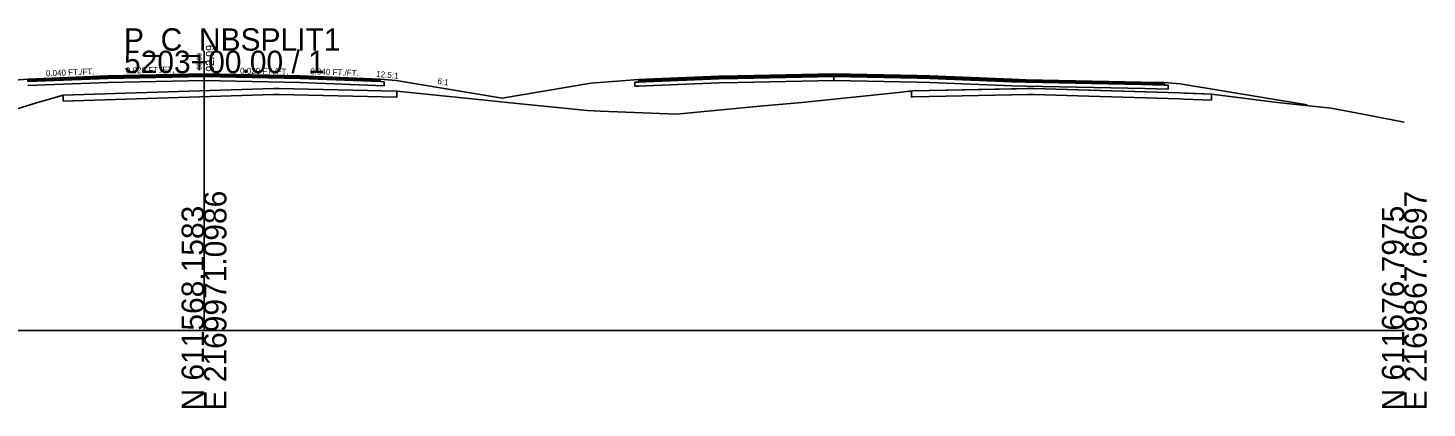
# Model space of a CAD drawing. Extents: x -26 to 1303, y -3010 to 12038.
# Drawn here: x 1128 to 1302.8, y 2490.3 to 2537.8 of the extents above; entities that cross this region are included whole.
import ezdxf

# ---------------------------------------------------------------- set-up
doc = ezdxf.new("R2010")
doc.units = 0
for name, color, linetype in [('RD_GPK_XS_Cell', 7, 'Continuous'), ('RD_XS_Base', 7, 'Continuous'), ('RD_XS_ExGround', 7, 'Continuous'), ('RD_XS_ExPaveRet', 7, 'Continuous'), ('RD_XS_Greenside', 7, 'Continuous'), ('RD_XS_Pave', 7, 'Continuous'), ('RD_XS_PaveOvlay_CP', 7, 'Continuous'), ('RD_XS_TieSlope', 7, 'Continuous'), ('RD_XS_TX_Elev_EX', 7, 'Continuous'), ('RD_XS_TX_Elev_PR', 7, 'Continuous'), ('RD_XS_TX_ShdSlope', 7, 'Continuous'), ('RD_XS_TX_Slope', 7, 'Continuous')]:
    doc.layers.add(name, color=color, linetype=linetype)

msp = doc.modelspace()

# ---------------------------------------------------------------- linework, layer by layer
at = {"layer": 'RD_GPK_XS_Cell'}
for p, q in [((1150, 2500), (1150, 2535)), ((1000, 2500), (1150, 2500)), ((1150, 2500), (1300, 2500))]:
    msp.add_line(p, q, dxfattribs=at)
at = {"layer": 'RD_XS_Base'}
for p, q in [((1150, 2531.77), (1138, 2531.53)), ((1150, 2531.77), (1150, 2531.93)), ((1150, 2531.93), (1150, 2531.93)), ((1150, 2531.93), (1150, 2531.93)), ((1150, 2531.93), (1150, 2531.27)), ((1150, 2531.27), (1150, 2531.77)), ((1150, 2531.77), (1150, 2531.77)), ((1150, 2531.77), (1150, 2531.77)), ((1150, 2531.77), (1150, 2531.77)), ((1162, 2531.53), (1150, 2531.77)), ((1228.71, 2531.77), (1216.71, 2531.53)), ((1228.71, 2531.79), (1228.71, 2531.93)), ((1228.71, 2531.93), (1228.71, 2531.35)), ((1228.71, 2531.77), (1228.71, 2531.79)), ((1228.71, 2531.77), (1228.71, 2531.77)), ((1239.11, 2531.56), (1228.71, 2531.77)), ((1228.71, 2531.77), (1228.71, 2531.77)), ((1228.71, 2531.33), (1228.71, 2531.77)), ((1138, 2531.53), (1128, 2531.13)), ((1128, 2531.13), (1128, 2531.13)), ((1128, 2530.63), (1138, 2531.03)), ((1128, 2530.63), (1128, 2530.63)), ((1138, 2531.53), (1138, 2531.53)), ((1138, 2531.03), (1150, 2531.27)), ((1138, 2531.03), (1138, 2531.03)), ((1150, 2531.27), (1150, 2531.27)), ((1150, 2531.27), (1150, 2531.27)), ((1150, 2531.27), (1162, 2531.03)), ((1172, 2531.13), (1162, 2531.53)), ((1162, 2531.03), (1172.5, 2530.61)), ((1164, 2531.45), (1164, 2531.45)), ((1164, 2530.95), (1164, 2530.95)), ((1172.5, 2531.11), (1172, 2531.13)), ((1172, 2531.13), (1172, 2531.13)), ((1172.5, 2530.61), (1172.5, 2531.11)), ((1172.5, 2531.11), (1172.5, 2531.11)), ((1203.89, 2531.06), (1203.85, 2531.06)), ((1203.85, 2531.06), (1203.85, 2530.6)), ((1203.85, 2530.6), (1203.85, 2530.56)), ((1203.85, 2530.56), (1203.89, 2530.56)), ((1204.35, 2531.08), (1203.89, 2531.06)), ((1203.89, 2530.56), (1204.35, 2530.58)), ((1205.2, 2531.12), (1204.35, 2531.08)), ((1204.35, 2530.58), (1205.2, 2530.62)), ((1214.35, 2531.48), (1205.2, 2531.12)), ((1205.2, 2530.62), (1214.35, 2530.98)), ((1216.71, 2531.53), (1214.35, 2531.48)), ((1214.35, 2530.98), (1216.71, 2531.03)), ((1216.71, 2531.03), (1228.71, 2531.27)), ((1228.71, 2531.35), (1228.71, 2531.27)), ((1228.71, 2531.27), (1228.71, 2531.33)), ((1228.71, 2531.27), (1239.11, 2531.06)), ((1240.71, 2531.53), (1239.11, 2531.56)), ((1239.11, 2531.06), (1240.71, 2531.03)), ((1250.95, 2531.12), (1240.71, 2531.53)), ((1240.71, 2531.03), (1250.95, 2530.62)), ((1252.71, 2531.05), (1250.95, 2531.12)), ((1250.95, 2530.62), (1252.71, 2530.55)), ((1267.17, 2530.76), (1252.71, 2531.05)), ((1252.71, 2530.55), (1267.58, 2530.25)), ((1270.01, 2530.7), (1267.17, 2530.76)), ((1267.58, 2530.25), (1270.51, 2530.19)), ((1270.42, 2530.69), (1270.01, 2530.7)), ((1270.51, 2530.69), (1270.42, 2530.69)), ((1270.51, 2530.28), (1270.51, 2530.69)), ((1270.51, 2530.19), (1270.51, 2530.28))]:
    msp.add_line(p, q, dxfattribs=at)
at = {"layer": 'RD_XS_ExGround'}
msp.add_lwpolyline([(1121.38, 2526.12), (1129.07, 2528.47), (1131.39, 2529.14), (1132.41, 2529.45), (1146.8, 2529.9), (1158.69, 2530.26), (1159.38, 2530.25), (1174.08, 2529.95), (1184.7, 2528.84), (1187.9, 2528.5), (1197.48, 2527.56), (1197.93, 2527.52), (1198.74, 2527.46), (1199.56, 2527.42), (1209.04, 2527.08), (1219.46, 2528.05), (1224.69, 2528.5), (1236.8, 2529.78), (1238.13, 2529.92), (1238.4, 2529.95), (1238.6, 2529.96), (1253.7, 2530.27), (1271.91, 2529.71), (1275.89, 2529.57), (1284.15, 2528.53), (1290.85, 2527.79), (1294.81, 2527.07), (1300, 2526.04)], dxfattribs=at)
at = {"layer": 'RD_XS_ExPaveRet'}
for p, q in [((1272.51, 2529.69), (1271.91, 2529.71)), ((1275.89, 2529.57), (1272.51, 2529.69))]:
    msp.add_line(p, q, dxfattribs=at)
for points in [[(1174.08, 2529.95), (1174.08, 2529.95), (1174.08, 2529.2), (1174.08, 2529.2), (1174.08, 2529.2), (1159.38, 2529.5), (1159.38, 2529.5), (1158.69, 2529.51), (1146.8, 2529.15), (1146.8, 2529.15), (1132.41, 2528.7), (1132.41, 2528.7), (1132.41, 2529.45), (1132.41, 2529.45), (1132.41, 2529.45), (1146.8, 2529.9), (1146.8, 2529.9), (1158.69, 2530.26), (1159.38, 2530.25), (1159.38, 2530.25), (1174.08, 2529.95), (1174.08, 2529.95), (1174.08, 2529.95)], [(1174.08, 2529.95), (1159.38, 2530.25), (1158.69, 2530.26), (1146.8, 2529.9), (1132.41, 2529.45), (1132.41, 2528.7), (1146.8, 2529.15), (1158.69, 2529.51), (1159.38, 2529.5), (1174.08, 2529.2), (1174.08, 2529.2), (1174.08, 2529.95), (1174.08, 2529.95)], [(1272.51, 2529.69), (1275.89, 2529.57), (1275.89, 2528.92), (1275.89, 2528.82), (1272.51, 2528.94), (1271.91, 2528.96), (1260.57, 2529.31), (1253.7, 2529.52), (1252.96, 2529.51), (1238.6, 2529.21), (1238.41, 2529.2), (1238.41, 2529.2), (1238.4, 2529.2), (1238.4, 2529.2), (1238.4, 2529.32), (1238.4, 2529.95), (1238.4, 2529.95), (1238.41, 2529.95), (1238.41, 2529.95), (1238.6, 2529.96), (1252.96, 2530.26), (1253.7, 2530.27), (1260.57, 2530.06), (1271.91, 2529.71), (1272.51, 2529.69)], [(1252.96, 2530.26), (1238.6, 2529.96), (1238.6, 2529.96), (1238.41, 2529.95), (1238.4, 2529.95)], [(1238.4, 2529.95), (1238.4, 2529.32), (1238.4, 2529.2), (1238.41, 2529.2), (1238.6, 2529.21), (1252.96, 2529.51), (1253.7, 2529.52), (1260.57, 2529.31), (1271.91, 2528.96), (1272.51, 2528.94), (1275.89, 2528.82), (1275.89, 2528.92), (1275.89, 2529.57)], [(1271.91, 2529.71), (1260.57, 2530.06), (1253.7, 2530.27), (1252.96, 2530.26)]]:
    msp.add_lwpolyline(points, dxfattribs=at)
at = {"layer": 'RD_XS_Greenside'}
for p, q in [((1174, 2531.29), (1187.28, 2529.08)), ((1198.35, 2530.92), (1187.28, 2529.08)), ((1272.01, 2530.86), (1287.87, 2528.22))]:
    msp.add_line(p, q, dxfattribs=at)
at = {"layer": 'RD_XS_Pave'}
for p, q in [((1138, 2531.85), (1128, 2531.45)), ((1138, 2531.69), (1128, 2531.29)), ((1128, 2531.29), (1138, 2531.69)), ((1150, 2532.09), (1138, 2531.85)), ((1150, 2531.93), (1138, 2531.69)), ((1138, 2531.69), (1150, 2531.93)), ((1138, 2531.85), (1138, 2531.85)), ((1138, 2531.53), (1150, 2531.77)), ((1138, 2531.69), (1138, 2531.69)), ((1138, 2531.69), (1138, 2531.69)), ((1162, 2531.85), (1150, 2532.09)), ((1150, 2532.09), (1150, 2532.09)), ((1150, 2532.09), (1150, 2532.09)), ((1150, 2531.77), (1150, 2531.93)), ((1150, 2531.93), (1150, 2531.93)), ((1150, 2531.93), (1150, 2531.93)), ((1150, 2531.93), (1150, 2531.93)), ((1150, 2531.93), (1150, 2531.93)), ((1150, 2531.93), (1162, 2531.69)), ((1162, 2531.69), (1150, 2531.93)), ((1150, 2531.93), (1150, 2531.93)), ((1150, 2531.93), (1150, 2531.93)), ((1150, 2531.93), (1150, 2531.77)), ((1150, 2531.77), (1150, 2531.77)), ((1150, 2531.77), (1150, 2531.77)), ((1150, 2531.77), (1162, 2531.53)), ((1172, 2531.45), (1162, 2531.85)), ((1162, 2531.69), (1172, 2531.29)), ((1172, 2531.29), (1162, 2531.69)), ((1164, 2531.77), (1164, 2531.77)), ((1214.35, 2531.8), (1205.2, 2531.43)), ((1216.71, 2531.85), (1214.35, 2531.8)), ((1216.71, 2531.69), (1214.35, 2531.64)), ((1214.35, 2531.64), (1216.71, 2531.69)), ((1228.71, 2532.09), (1216.71, 2531.85)), ((1228.71, 2531.93), (1216.71, 2531.69)), ((1216.71, 2531.69), (1228.71, 2531.93)), ((1216.71, 2531.53), (1228.71, 2531.77)), ((1239.11, 2531.88), (1228.71, 2532.09)), ((1228.71, 2531.79), (1228.71, 2531.93)), ((1228.71, 2531.93), (1239.11, 2531.72)), ((1239.11, 2531.72), (1228.71, 2531.93)), ((1228.71, 2531.93), (1228.71, 2531.93)), ((1228.71, 2531.93), (1228.71, 2531.93)), ((1228.71, 2531.93), (1228.71, 2531.79)), ((1228.71, 2531.77), (1228.71, 2531.79)), ((1228.71, 2531.79), (1228.71, 2531.77)), ((1228.71, 2531.77), (1228.71, 2531.77)), ((1228.71, 2531.77), (1228.71, 2531.77)), ((1228.71, 2531.77), (1239.11, 2531.56)), ((1240.71, 2531.85), (1239.11, 2531.88)), ((1239.11, 2531.72), (1240.71, 2531.69)), ((1240.71, 2531.69), (1239.11, 2531.72)), ((1250.95, 2531.44), (1240.71, 2531.85)), ((1240.71, 2531.69), (1250.95, 2531.28)), ((1250.95, 2531.28), (1240.71, 2531.69)), ((1128, 2531.13), (1138, 2531.53)), ((1128, 2531.45), (1128, 2531.45)), ((1128, 2531.45), (1128, 2531.29)), ((1128, 2531.29), (1128, 2531.29)), ((1128, 2531.29), (1128, 2531.13)), ((1138, 2531.53), (1138, 2531.53)), ((1162, 2531.53), (1172, 2531.13)), ((1164, 2531.61), (1164, 2531.61)), ((1164, 2531.61), (1164, 2531.61)), ((1164, 2531.45), (1164, 2531.45)), ((1172, 2531.29), (1172, 2531.45)), ((1172, 2531.45), (1172, 2531.45)), ((1172, 2531.13), (1172, 2531.29)), ((1172, 2531.29), (1172, 2531.29)), ((1205.2, 2531.43), (1204.35, 2531.4)), ((1204.35, 2531.4), (1204.35, 2531.26)), ((1205.2, 2531.28), (1204.35, 2531.24)), ((1204.35, 2531.24), (1205.2, 2531.28)), ((1204.35, 2531.26), (1204.35, 2531.24)), ((1204.35, 2531.24), (1204.35, 2531.1)), ((1204.35, 2531.08), (1205.2, 2531.12)), ((1204.35, 2531.1), (1204.35, 2531.08)), ((1214.35, 2531.64), (1205.2, 2531.28)), ((1205.2, 2531.28), (1214.35, 2531.64)), ((1205.2, 2531.12), (1214.35, 2531.48)), ((1214.35, 2531.48), (1216.71, 2531.53)), ((1239.11, 2531.56), (1240.71, 2531.53)), ((1240.71, 2531.53), (1250.95, 2531.12)), ((1252.71, 2531.37), (1250.95, 2531.44)), ((1250.95, 2531.28), (1252.71, 2531.21)), ((1252.71, 2531.21), (1250.95, 2531.28)), ((1250.95, 2531.12), (1252.71, 2531.05)), ((1267.17, 2531.08), (1252.71, 2531.37)), ((1252.71, 2531.21), (1267.17, 2530.92)), ((1267.17, 2530.92), (1252.71, 2531.21)), ((1252.71, 2531.05), (1267.17, 2530.76)), ((1270.01, 2531.02), (1267.17, 2531.08)), ((1267.17, 2530.92), (1270.01, 2530.86)), ((1270.01, 2530.86), (1267.17, 2530.92)), ((1267.17, 2530.76), (1270.01, 2530.7)), ((1270.01, 2530.89), (1270.01, 2531.02)), ((1270.01, 2530.86), (1270.01, 2530.89)), ((1270.01, 2530.73), (1270.01, 2530.86)), ((1270.01, 2530.7), (1270.01, 2530.73))]:
    msp.add_line(p, q, dxfattribs=at)
at = {"layer": 'RD_XS_PaveOvlay_CP'}
for p, q in [((1128, 2531.45), (1138, 2531.85)), ((1138, 2531.85), (1150, 2532.09)), ((1150, 2532.09), (1162, 2531.85)), ((1162, 2531.85), (1172, 2531.45)), ((1214.35, 2531.8), (1205.2, 2531.43)), ((1216.71, 2531.85), (1214.35, 2531.8)), ((1228.71, 2532.09), (1216.71, 2531.85)), ((1239.11, 2531.88), (1228.71, 2532.09)), ((1240.71, 2531.85), (1239.11, 2531.88)), ((1250.95, 2531.44), (1240.71, 2531.85)), ((1205.2, 2531.43), (1204.35, 2531.4)), ((1252.71, 2531.37), (1250.95, 2531.44)), ((1267.17, 2531.08), (1252.71, 2531.37)), ((1270.01, 2531.02), (1267.17, 2531.08))]:
    msp.add_line(p, q, dxfattribs=at)
at = {"layer": 'RD_XS_TieSlope'}
for p, q in [((1128, 2531.45), (1122.3, 2530.99)), ((1172, 2531.45), (1174, 2531.29)), ((1204.35, 2531.4), (1198.35, 2530.92)), ((1270.01, 2531.02), (1272.01, 2530.86))]:
    msp.add_line(p, q, dxfattribs=at)

# ---------------------------------------------------------------- texts
at = {"layer": 'RD_GPK_XS_Cell'}
for s, p in [('P_C_NBSPLIT1', (1140, 2535)), ('5203+00.00 / 1', (1140, 2532.2))]:
    msp.add_text(s, height=2.8, dxfattribs=at).set_placement(p)
for s, p in [('E 2169971.0986', (1152.8, 2490)), ('E 2169867.6697', (1302.8, 2490)), ('N 611568.1583', (1150, 2490)), ('N 611676.7975', (1300, 2490))]:
    msp.add_text(s, height=2.8, rotation=90, dxfattribs=at).set_placement(p)
at = {"layer": 'RD_XS_TX_Elev_EX'}
msp.add_text('90.00', height=0.6, rotation=90, dxfattribs=at).set_placement((1149.69, 2532.62))
at = {"layer": 'RD_XS_TX_Elev_PR'}
msp.add_text('92.09', height=1, rotation=90, dxfattribs=at).set_placement((1151.23, 2532.37))
at = {"layer": 'RD_XS_TX_ShdSlope'}
msp.add_text('12.5:1', height=0.75, rotation=355.4261, dxfattribs=at).set_placement((1171.5, 2531.72))
at = {"layer": 'RD_XS_TX_Slope'}
for s, rotation, p in [('0.040 FT./FT.', 2.2906, (1130.25, 2531.8)), ('0.020 FT./FT.', 1.1458, (1140.25, 2532.15)), ('0.020 FT./FT.', 358.8542, (1154.5, 2532.12)), ('0.040 FT./FT.', 357.7094, (1163.26, 2532.06)), ('6:1', 350.5377, (1179.13, 2530.86))]:
    msp.add_text(s, height=0.75, rotation=rotation, dxfattribs=at).set_placement(p)

doc.saveas('drawing.dxf')
